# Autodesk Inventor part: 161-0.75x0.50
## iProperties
Created: 2007-06
Part Number: 161-0.75x0.50
Document SubType Name: Modeling
Designer: btaylor
Density: 1 g/cm^3
Author: btaylor
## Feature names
1. Extrusion1
2. Extrusion2
3. Extrusion3
4. Extrusion4
5. Extrusion5
6. Fillet1
7. Fillet2
8. Fillet3
9. Fillet4
10. Fillet5
11. Fillet6
12. Extrusion6
13. Extrusion7
14. Extrusion8
15. Extrusion9
16. Extrusion10
17. Fillet7
18. Fillet8
19. Fillet9
20. Fillet10
21. Chamfer1
22. Chamfer2
23. Chamfer3
24. Fillet11
25. Fillet12
26. Fillet13
